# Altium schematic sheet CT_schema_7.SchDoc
size 367 x 243 mm
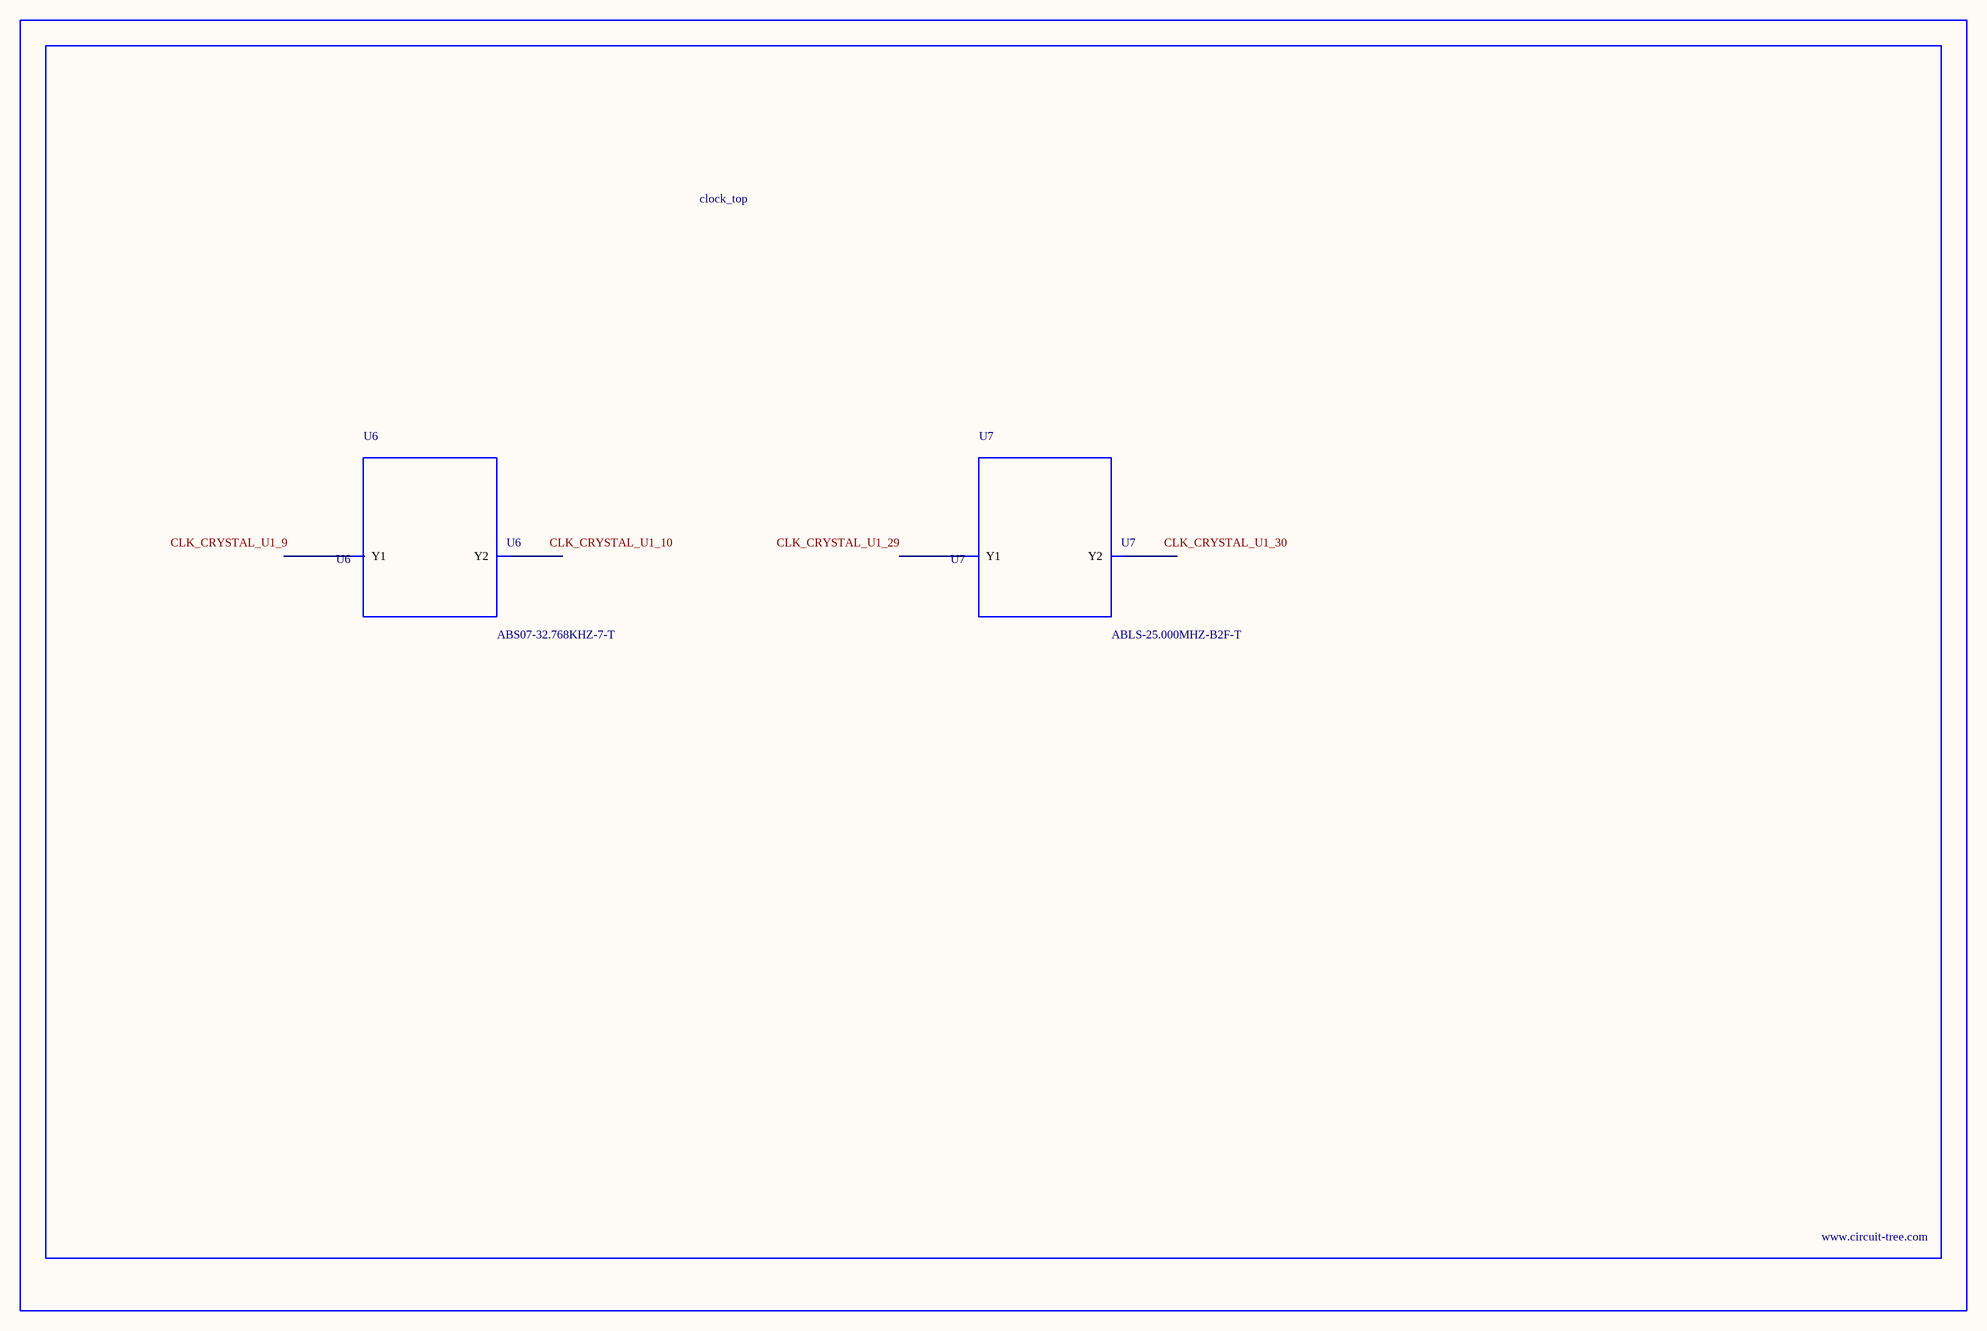
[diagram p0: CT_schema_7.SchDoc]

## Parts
BORDER6  (no value)
U6  ABS07-32.768KHZ-7-T  [ABS07-32.768KHZ-7-T]
U7  ABLS-25.000MHZ-B2F-T  [ABLS-25.000MHZ-B2F-T]

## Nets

Not connected (* = marked no-connect by the designer): U6 1(Y1) 2(Y2); U7 1(Y1) 2(Y2)

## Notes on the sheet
- Labels drawn without touching a wire or pin: CLK_CRYSTAL_U1_9, CLK_CRYSTAL_U1_10, CLK_CRYSTAL_U1_29, CLK_CRYSTAL_U1_30

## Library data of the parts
BORDER6 = BORDER_PAGE6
